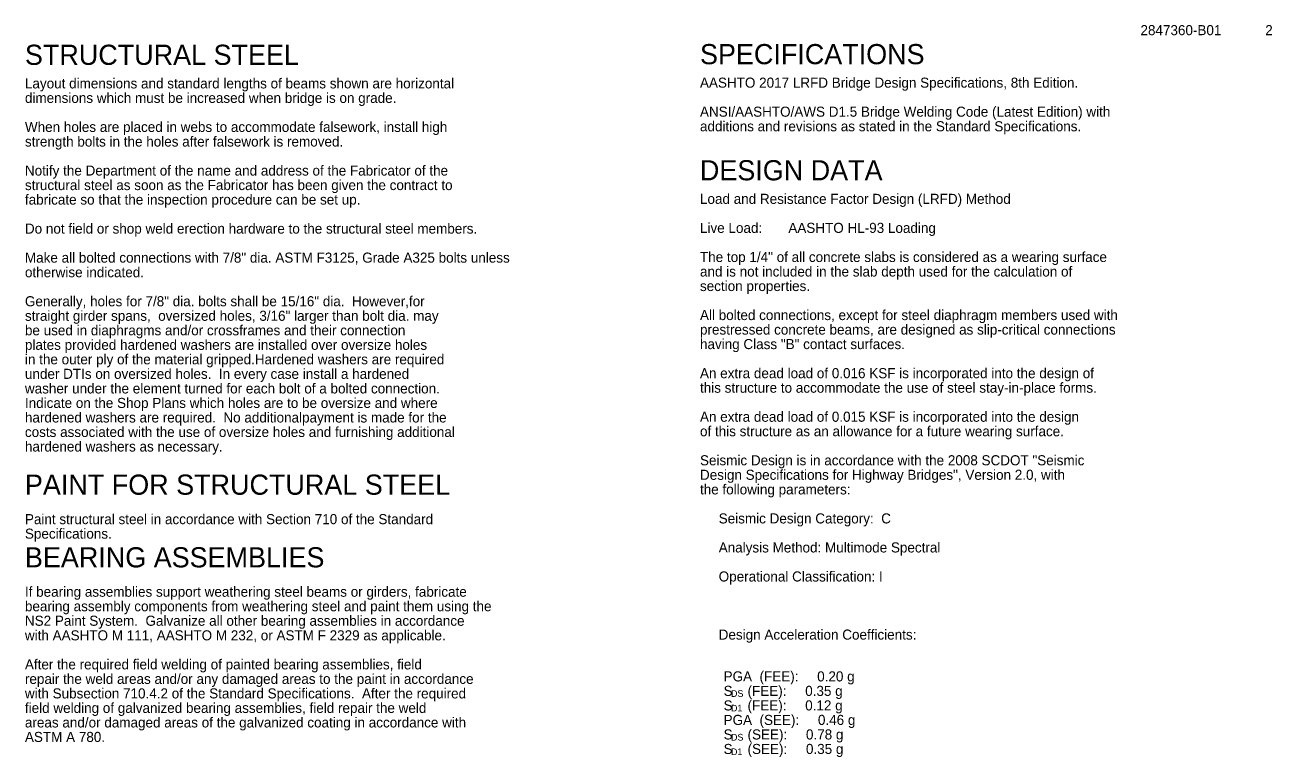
# Model space of a CAD drawing. Extents: x 0.5 to 33.9, y 1.3 to 22.
# Drawn here: x 18.35 to 33.82, y 12.49 to 21.56 of the extents above; entities that cross this region are included whole.
import ezdxf

# ---------------------------------------------------------------- set-up
doc = ezdxf.new("R2010")
doc.units = 0
doc.layers.add('BR_TEXT', color=7, linetype='Continuous')

msp = doc.modelspace()

# ---------------------------------------------------------------- texts
at = {"layer": 'BR_TEXT'}
for s, height, p in [('2847360-B01', 0.125, (32.19, 21.437)), ('2', 0.125, (33.738, 21.437)), ('STRUCTURAL STEEL', 0.25, (18.35, 21.069)), ('SPECIFICATIONS', 0.25, (26.725, 21.077)), ('Layout dimensions and standard lengths of beams shown are horizontal ', 0.125, (18.35, 20.777)), ('AASHTO 2017 LRFD Bridge Design Specifications, 8th Edition.', 0.125, (26.725, 20.786)), ('dimensions which must be increased when bridge is on grade.', 0.125, (18.35, 20.597)), ('ANSI/AASHTO/AWS D1.5 Bridge Welding Code (Latest Edition) with', 0.125, (26.725, 20.426)), ('When holes are placed in webs to accommodate falsework, install high', 0.125, (18.35, 20.237)), ('additions and revisions as stated in the Standard Specifications.', 0.125, (26.725, 20.245)), ('strength bolts in the holes after falsework is removed.', 0.125, (18.35, 20.056)), ('Notify the Department of the name and address of the Fabricator of the ', 0.125, (18.35, 19.696)), ('DESIGN DATA', 0.25, (26.724, 19.637)), ('structural steel as soon as the Fabricator has been given the contract to ', 0.125, (18.35, 19.516)), ('fabricate so that the inspection procedure can be set up.', 0.125, (18.35, 19.336)), ('Load and Resistance Factor Design (LRFD) Method', 0.125, (26.725, 19.345)), ('Do not field or shop weld erection hardware to the structural steel members. ', 0.125, (18.35, 18.976)), ('Live Load:       AASHTO HL-93 Loading ', 0.125, (26.725, 18.985)), ('Make all bolted connections with 7/8" dia. ASTM F3125, Grade A325 bolts unless', 0.125, (18.35, 18.616)), ('The top 1/4" of all concrete slabs is considered as a wearing surface ', 0.125, (26.725, 18.624)), ('otherwise indicated.', 0.125, (18.35, 18.435)), ('and is not included in the slab depth used for the calculation of ', 0.125, (26.725, 18.444)), ('section properties.', 0.125, (26.725, 18.264)), ('Generally, holes for 7/8" dia. bolts shall be 15/16" dia.  However,for ', 0.125, (18.35, 18.075)), ('straight girder spans,  oversized holes, 3/16" larger than bolt dia. may ', 0.125, (18.35, 17.895)), ('All bolted connections, except for steel diaphragm members used with', 0.125, (26.725, 17.904)), ('be used in diaphragms and/or crossframes and their connection ', 0.125, (18.35, 17.715)), ('prestressed concrete beams, are designed as slip-critical connections', 0.125, (26.725, 17.724)), ('plates provided hardened washers are installed over oversize holes', 0.125, (18.35, 17.535)), ('having Class "B" contact surfaces.', 0.125, (26.725, 17.544)), ('in the outer ply of the material gripped.Hardened washers are required', 0.125, (18.35, 17.355)), ('under DTIs on oversized holes.  In every case install a hardened ', 0.125, (18.35, 17.175)), ('An extra dead load of 0.016 KSF is incorporated into the design of ', 0.125, (26.725, 17.183)), ('washer under the element turned for each bolt of a bolted connection.  ', 0.125, (18.35, 16.994)), ('this structure to accommodate the use of steel stay-in-place forms.', 0.125, (26.725, 17.003)), ('Indicate on the Shop Plans which holes are to be oversize and where ', 0.125, (18.35, 16.814)), ('hardened washers are required.  No additionalpayment is made for the ', 0.125, (18.35, 16.634)), ('An extra dead load of 0.015 KSF is incorporated into the design', 0.125, (26.725, 16.643)), ('costs associated with the use of oversize holes and furnishing additional ', 0.125, (18.35, 16.454)), ('of this structure as an allowance for a future wearing surface.', 0.125, (26.725, 16.463)), ('hardened washers as necessary.', 0.125, (18.35, 16.274)), ('Seismic Design is in accordance with the 2008 SCDOT "Seismic', 0.125, (26.725, 16.103)), ('PAINT FOR STRUCTURAL STEEL', 0.25, (18.35, 15.738)), ('Design Specifications for Highway Bridges", Version 2.0, with', 0.125, (26.725, 15.923)), ('the following parameters:', 0.125, (26.725, 15.742)), ('Paint structural steel in accordance with Section 710 of the Standard ', 0.125, (18.35, 15.373)), ('     Seismic Design Category:  C', 0.125, (26.725, 15.382)), ('Specifications.', 0.125, (18.35, 15.193)), ('BEARING ASSEMBLIES', 0.25, (18.35, 14.837)), ('     Analysis Method: Multimode Spectral', 0.125, (26.725, 15.022)), ('     Operational Classification: I', 0.125, (26.725, 14.662)), ('If bearing assemblies support weathering steel beams or girders, fabricate ', 0.125, (18.35, 14.473)), ('bearing assembly components from weathering steel and paint them using the ', 0.125, (18.35, 14.293)), ('NS2 Paint System.  Galvanize all other bearing assemblies in accordance ', 0.125, (18.35, 14.113)), ('with AASHTO M 111, AASHTO M 232, or ASTM F 2329 as applicable. ', 0.125, (18.35, 13.932)), ('     Design Acceleration Coefficients:', 0.125, (26.725, 13.941)), ('After the required field welding of painted bearing assemblies, field ', 0.125, (18.35, 13.572)), ('repair the weld areas and/or any damaged areas to the paint in accordance ', 0.125, (18.35, 13.392)), ('PGA  (FEE):     0.20 g', 0.125, (27.018, 13.423)), ('with Subsection 710.4.2 of the Standard Specifications.  After the required ', 0.125, (18.35, 13.212)), ('S    (FEE):     0.35 g', 0.125, (27.018, 13.243)), ('DS', 0.0833, (27.109, 13.231)), ('field welding of galvanized bearing assemblies, field repair the weld ', 0.125, (18.35, 13.032)), ('S    (FEE):     0.12 g', 0.125, (27.018, 13.063)), ('PGA  (SEE):     0.46 g', 0.125, (27.018, 12.883)), ('D1', 0.0833, (27.109, 13.05)), ('areas and/or damaged areas of the galvanized coating in accordance with ', 0.125, (18.35, 12.852)), ('ASTM A 780.', 0.125, (18.35, 12.672)), ('S    (SEE):     0.78 g', 0.125, (27.018, 12.703)), ('DS', 0.0833, (27.109, 12.689)), ('S    (SEE):     0.35 g', 0.125, (27.018, 12.523)), ('D1', 0.0833, (27.109, 12.509))]:
    msp.add_text(s, height=height, dxfattribs=at).set_placement(p)

doc.saveas('drawing.dxf')
